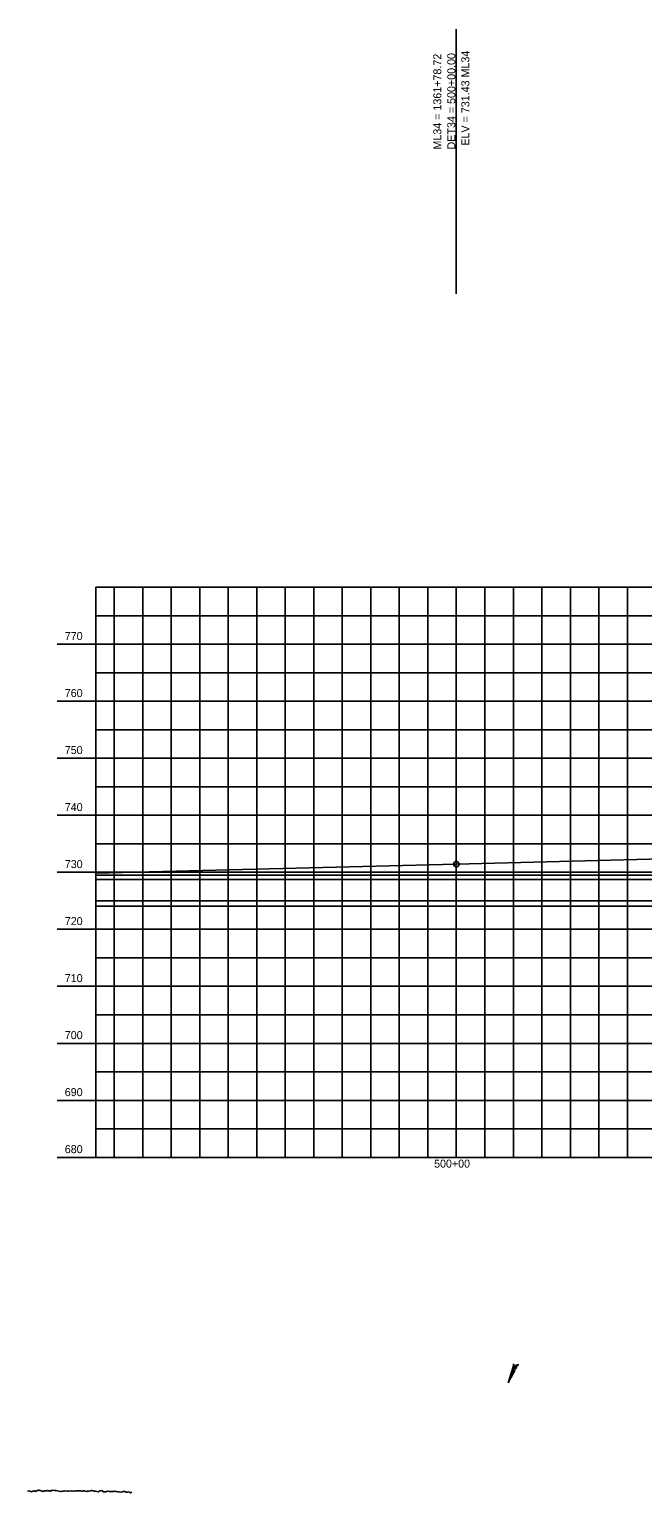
# Model space of a CAD drawing. Extents: x -6486 to 2300, y -1487 to 2659.
# Drawn here: x -749 to 327, y 92 to 2659 of the extents above; entities that cross this region are included whole.
import ezdxf

# ---------------------------------------------------------------- set-up
doc = ezdxf.new("R2010")
doc.units = 0
for name, color, linetype in [('Contours Major', 7, 'Continuous'), ('DisROW Survey', 7, 'Continuous'), ('EdgePaved', 7, 'Continuous'), ('Fence', 7, 'Continuous'), ('PhoEdgeParkingUnpaved', 7, 'Continuous'), ('phoSurveyPoints', 7, 'Continuous'), ('Section Lines', 7, 'Continuous'), ('SheetGridMajor', 7, 'Continuous'), ('SurPointsNonDTM', 7, 'Continuous'), ('Text', 7, 'Continuous'), ('TL_GroundIntercept', 7, 'Continuous')]:
    doc.layers.add(name, color=color, linetype=linetype)

msp = doc.modelspace()

# ---------------------------------------------------------------- linework, layer by layer
at = {"layer": 'Contours Major'}
for p, q in [((-632.5, 1680), (2232.5, 1680)), ((-632.5, 680), (-632.5, 1680)), ((-632.5, 680), (2232.5, 680))]:
    msp.add_line(p, q, dxfattribs=at)
at = {"layer": 'DisROW Survey'}
msp.add_line((-632.5, 1120.3), (2232.5, 1120.3), dxfattribs=at)
at = {"layer": 'EdgePaved'}
for p, q in [((-600, 680), (-600, 1680)), ((-550, 680), (-550, 1680)), ((-450, 680), (-450, 1680)), ((-400, 680), (-400, 1680)), ((-350, 680), (-350, 1680)), ((-300, 680), (-300, 1680)), ((-250, 680), (-250, 1680)), ((-200, 680), (-200, 1680)), ((-150, 680), (-150, 1680)), ((-100, 680), (-100, 1680)), ((-50, 680), (-50, 1680)), ((50, 680), (50, 1680)), ((100, 680), (100, 1680)), ((150, 680), (150, 1680)), ((200, 680), (200, 1680)), ((250, 680), (250, 1680)), ((300, 680), (300, 1680)), ((-632.5, 1630), (2232.5, 1630)), ((-632.5, 1530), (2232.5, 1530)), ((-632.5, 1430), (2232.5, 1430)), ((-632.5, 1330), (2232.5, 1330)), ((-632.5, 1230), (2232.5, 1230)), ((-632.5, 1130), (2232.5, 1130)), ((-632.5, 1030), (2232.5, 1030)), ((-632.5, 930), (2232.5, 930)), ((-632.5, 830), (2232.5, 830)), ((-632.5, 730), (2232.5, 730))]:
    msp.add_line(p, q, dxfattribs=at)
at = {"layer": 'Fence'}
for p, q in [((91.2, 284.7), (100.4, 314.6)), ((100.4, 314.6), (92, 286.2)), ((94, 289.6), (100.4, 314.6)), ((100.4, 314.6), (95.9, 293)), ((97.9, 296.3), (100.4, 314.6)), ((100.4, 314.6), (99.4, 298.9)), ((100.4, 314.6), (100.4, 317.8)), ((100.4, 314.6), (109.6, 316.5)), ((100.4, 314.6), (108.7, 315)), ((106.7, 311.6), (100.4, 314.6)), ((104.8, 308.3), (100.4, 314.6)), ((100.4, 314.6), (102.8, 304.9)), ((101.3, 302.3), (100.4, 314.6))]:
    msp.add_line(p, q, dxfattribs=at)
at = {"layer": 'PhoEdgeParkingUnpaved'}
msp.add_lwpolyline([(-752.2, 95), (-747.9, 94.4), (-746.8, 94.3), (-745.6, 93.1), (-740.5, 95.4), (-740, 95.5), (-739.7, 95.4), (-737.8, 94.1), (-735.5, 95.7), (-733.1, 96.3), (-731.7, 96.4), (-730.3, 95.2), (-730.3, 95.2), (-729.1, 95.8), (-725.5, 94.1), (-723.5, 94.8), (-723.3, 94.8), (-722.6, 95), (-718, 95.3), (-716.9, 95.8), (-715.6, 95.2), (-712.4, 95), (-711.2, 94.5), (-710.5, 95.4), (-708.9, 96.3), (-704.9, 95.7), (-704, 95.6), (-703.3, 95.6), (-701.8, 95.6), (-699.7, 95.2), (-697, 94.3), (-694.3, 94.1), (-694.2, 94.2), (-693.7, 94.1), (-693.4, 94.2), (-689.9, 94.3), (-687.6, 95.1), (-687.5, 95.1), (-682.7, 94.8), (-682.5, 94.8), (-682.5, 94.8), (-680.2, 94.6), (-676.9, 95), (-676, 94.8), (-675.3, 94.9), (-673.4, 94.7), (-670.9, 94.9), (-668.9, 94.7), (-667.7, 95), (-666.7, 94.7), (-664.9, 94.9), (-661.9, 95), (-660, 95.2), (-659.7, 95.2), (-659.2, 95.2), (-656.4, 94.5), (-655.3, 94.3), (-653.8, 94.9), (-653.1, 95.2), (-652.8, 95.2), (-648.6, 93.9), (-646.9, 94.7), (-646.3, 94.6), (-644.6, 94.7), (-641.8, 94.9), (-640.2, 95.7), (-639.2, 95.8), (-637, 95.4), (-635.1, 94.8), (-634.2, 94.7), (-633, 94.7), (-628, 93.5), (-627.9, 93.5), (-627.7, 93.5), (-625.8, 95), (-623.4, 95.3), (-621.4, 95.5), (-619.4, 93.6), (-619.1, 93.3), (-618.9, 93.1), (-618.7, 93.1), (-614.7, 93.5), (-612.7, 94.8), (-612.4, 94.9), (-611.6, 94.6), (-607.7, 93.9), (-606.6, 93.5), (-605.3, 93.9), (-601.4, 94.2), (-601.1, 94.2), (-600.9, 94.2), (-598.8, 94.8), (-596.7, 93.9), (-594, 93.4), (-592.3, 93.3), (-591.9, 93.4), (-591.5, 93.5), (-587.4, 93), (-586.2, 92.9), (-584.9, 93.8), (-581.4, 93.8), (-580.8, 93.8), (-580.2, 93.3), (-578.5, 92.5), (-576.5, 92.9), (-573.6, 93.3), (-572.7, 92), (-571.7, 91.8), (-569.4, 92.7)], dxfattribs=at)
at = {"layer": 'Section Lines'}
msp.add_line((-632.5, 1175), (2232.5, 1175), dxfattribs=at)
at = {"layer": 'SheetGridMajor'}
for p, q in [((0, 2194.3), (0, 2658.6)), ((0, 1194.3), (569.1, 1208.6)), ((-632.5, 1178.5), (0, 1194.3))]:
    msp.add_line(p, q, dxfattribs=at)
msp.add_circle((0, 1194.3), 4.86, dxfattribs=at)
at = {"layer": 'Text'}
msp.add_line((-632.5, 1167.2), (2232.5, 1167.2), dxfattribs=at)
at = {"layer": 'TL_GroundIntercept'}
for p, q in [((-500, 680), (-500, 1680)), ((0, 680), (0, 1680)), ((-632.5, 1580), (-700, 1580)), ((-632.5, 1580), (2232.5, 1580)), ((-632.5, 1480), (-700, 1480)), ((-632.5, 1480), (2232.5, 1480)), ((-632.5, 1380), (-700, 1380)), ((-632.5, 1380), (2232.5, 1380)), ((-632.5, 1280), (-700, 1280)), ((-632.5, 1280), (2232.5, 1280)), ((-632.5, 1180), (-700, 1180)), ((-632.5, 1180), (2232.5, 1180)), ((-632.5, 1080), (-700, 1080)), ((-632.5, 1080), (2232.5, 1080)), ((-632.5, 980), (-700, 980)), ((-632.5, 980), (2232.5, 980)), ((-632.5, 880), (-700, 880)), ((-632.5, 880), (2232.5, 880)), ((-632.5, 780), (-700, 780)), ((-632.5, 780), (2232.5, 780)), ((-632.5, 680), (-700, 680))]:
    msp.add_line(p, q, dxfattribs=at)

# ---------------------------------------------------------------- texts
at = {"layer": 'phoSurveyPoints'}
for s, p in [('730.57', (72.4, 680)), ('730.56', (97.4, 680)), ('730.56', (122.4, 680)), ('730.55', (147.4, 680)), ('730.55', (172.4, 680)), ('730.54', (197.4, 680)), ('730.54', (222.4, 680)), ('730.53', (247.4, 680)), ('730.53', (272.4, 680)), ('730.52', (297.4, 680)), ('730.52', (322.4, 680))]:
    msp.add_text(s, height=0.0125, rotation=90, dxfattribs=at).set_placement(p)
at = {"layer": 'SheetGridMajor'}
for s, p in [('ELV = 731.43 ML34', (22.8, 2454.5)), ('ML34 = 1361+78.72', (-26.3, 2447.6)), ('DET34 = 500+00.00', (-1.8, 2447.8))]:
    msp.add_text(s, height=14.04, rotation=90, dxfattribs=at).set_placement(p)
at = {"layer": 'SurPointsNonDTM'}
for s, height, p in [('770', 14.04, (-686.8, 1587.4)), ('760', 14.04, (-686.8, 1487.4)), ('750', 14.04, (-686.8, 1387.4)), ('740', 14.04, (-686.8, 1287.4)), ('730', 14.04, (-686.8, 1187.4)), ('720', 14.04, (-686.8, 1087.4)), ('710', 14.04, (-686.8, 987.4)), ('700', 14.04, (-686.8, 887.4)), ('690', 14.04, (-686.8, 787.4)), ('680', 14.04, (-686.8, 687.4)), ('500+00', 14, (-39, 662))]:
    msp.add_text(s, height=height, dxfattribs=at).set_placement(p)

doc.saveas('drawing.dxf')
